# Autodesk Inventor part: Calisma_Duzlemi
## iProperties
Company: Autodesk, Inc.
Shininess: 64.0
Length Units: 11269
Angle Units: 11279
Time Units: 11290
Mass Units: 11283
Length Display Precision: 3
Angle Display Precision: 2
Compacted: True
Part Number: Calisma_Duzlemi
Document SubType Name: Modeling
Created: 2003-11
Catalog Web Link: www.autodesk.com
Vendor: Autodesk, Inc.
Designer: Administrator
Manufacturer: Standard
Standards Organization: Custom
Density: 1 g/cm^3
Density: 0.0
Volumn: 0.0
Area: 0.0
PropertySet Name: Model Information
Control State: 0
Master: False
Checked Out: False
Author: Administrator
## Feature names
1. Extrusion1
2. Extrusion2
